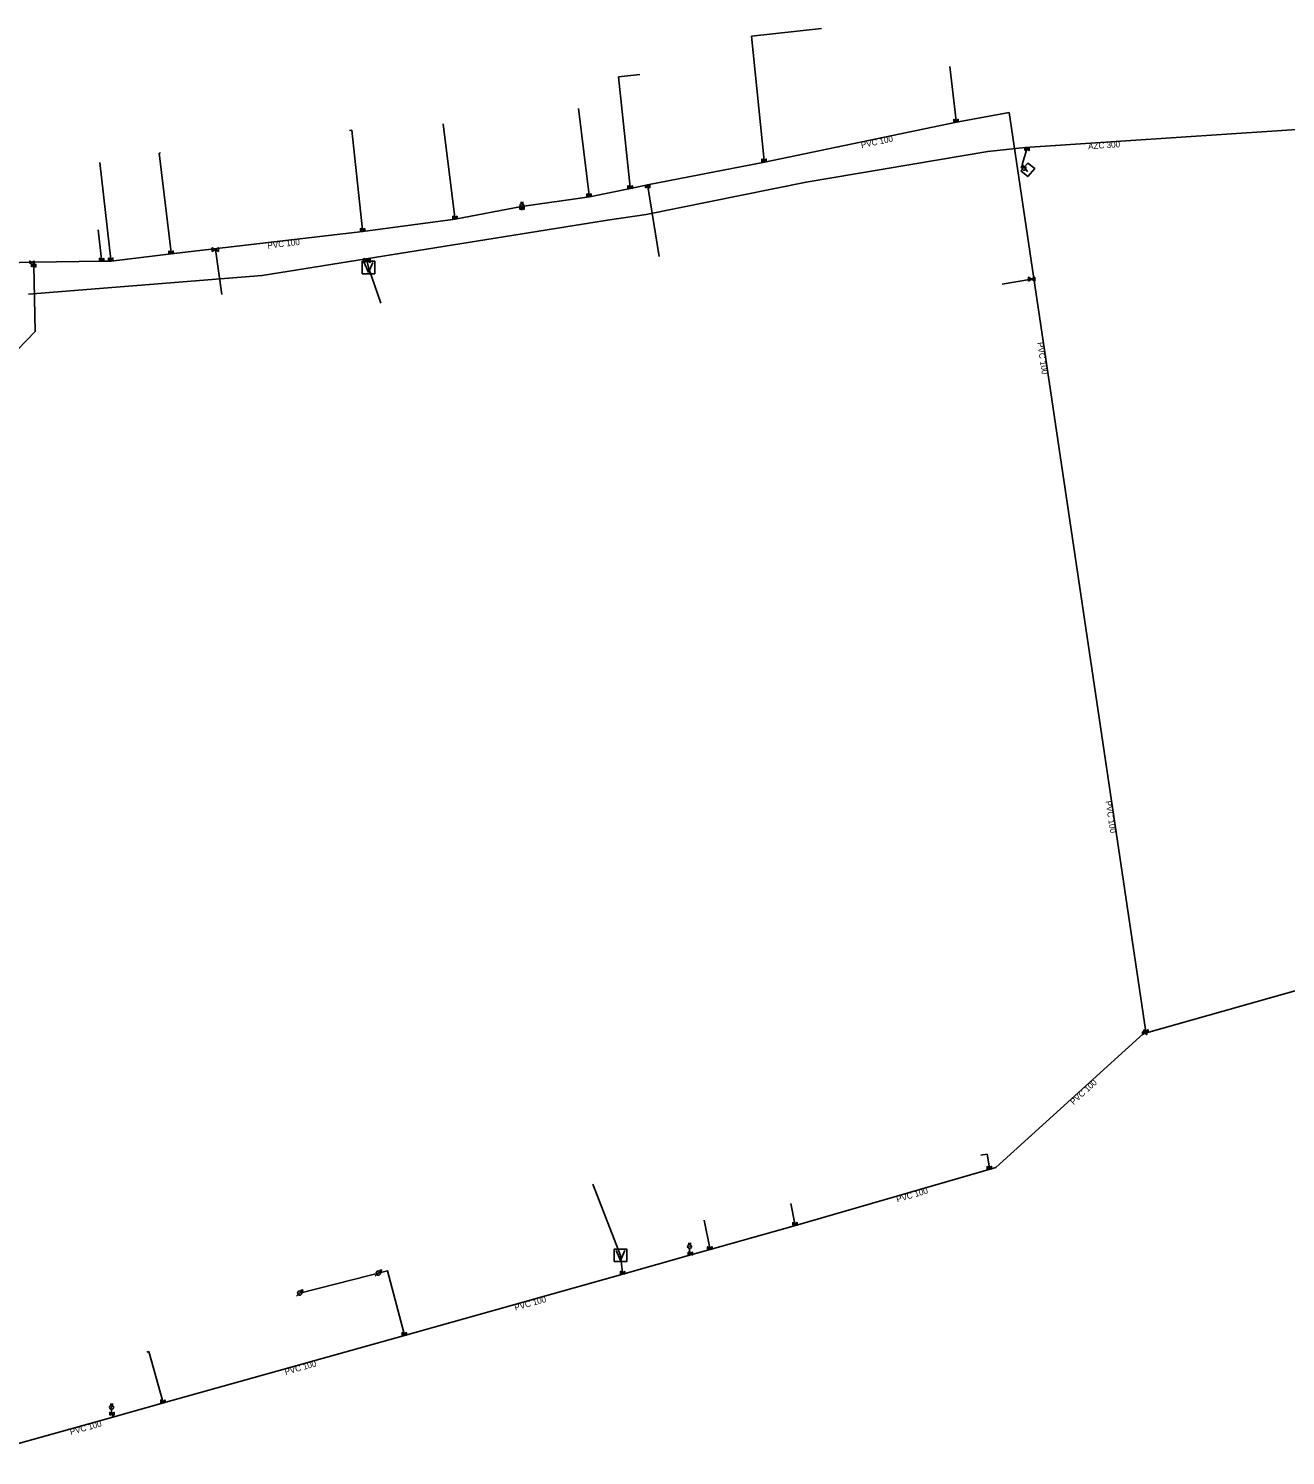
# Model space of a CAD drawing. Extents: x -523120 to -513568, y -1130571 to -1128904.
# Drawn here: x -518438 to -518236.1, y -1130098.8 to -1129869.7 of the extents above; entities that cross this region are included whole.
import ezdxf

# ---------------------------------------------------------------- set-up
doc = ezdxf.new("R2010")
doc.units = 0
for name, color, linetype in [('Default', 7, 'Continuous'), ('MoLevel 10', 7, 'Continuous'), ('MoLevel 11', 7, 'Continuous'), ('MoLevel 12', 7, 'Continuous'), ('MoLevel 13', 7, 'Continuous'), ('MoLevel 15', 7, 'Continuous'), ('MoLevel 17', 7, 'Continuous'), ('MoLevel 32', 7, 'Continuous')]:
    doc.layers.add(name, color=color, linetype=linetype)

# ---------------------------------------------------------------- blocks, each defined once
blk = doc.blocks.new('0.10')
at = {"layer": 'Default'}
for p, q in [((-0.00005, -0.00005), (0.00005, 0.00005)), ((0.00005, 0.00005), (0.00002, 0.000045)), ((0.00005, 0.00005), (0.000045, 0.00002))]:
    blk.add_line(p, q, dxfattribs=at)
blk.add_circle((0, 0), 0.000035, dxfattribs=at)
blk = doc.blocks.new('0.01')
at = {"layer": 'Default'}
blk.add_lwpolyline([(-0.00005, -0.00003), (0.00005, 0.00003), (0.00005, -0.00003), (-0.00005, 0.00003), (-0.00005, -0.00003)], dxfattribs=at)
blk = doc.blocks.new('0.05')
at = {"layer": 'Default'}
for p, q in [((-0.00001, 0.00005), (0.00001, 0.00005)), ((-0.000009, 0.000021), (0.000009, 0.000039)), ((0, 0.0000425), (0, 0.00005)), ((0, 0), (0, 0.0000175))]:
    blk.add_line(p, q, dxfattribs=at)
blk.add_circle((0, 0.00003), 0.0000125, dxfattribs=at)
blk = doc.blocks.new('0.04')
at = {"layer": 'Default'}
for p, q in [((-0.00001, 0.00005), (0.00001, 0.00005)), ((0, 0.0000425), (0, 0.00005)), ((0, 0), (0, 0.0000175))]:
    blk.add_line(p, q, dxfattribs=at)
blk.add_circle((0, 0.00003), 0.0000125, dxfattribs=at)
blk = doc.blocks.new('0.12')
at = {"layer": 'Default'}
for q in [(-0.000035, 0.00004), (0.000035, 0.00004)]:
    blk.add_line((0, -0.00004), q, dxfattribs=at)
blk.add_lwpolyline([(-0.00005, -0.00005), (0.00005, -0.00005), (0.00005, 0.00005), (-0.00005, 0.00005), (-0.00005, -0.00005)], dxfattribs=at)

msp = doc.modelspace()

# ---------------------------------------------------------------- linework, layer by layer
at = {"layer": 'MoLevel 10'}
for p, q in [((-518288.98, -1129884.77), (-518280.52, -1129883.17)), ((-518280.52, -1129883.17), (-518258.57, -1130030.46)), ((-518319.81, -1129891.14), (-518288.98, -1129884.77)), ((-518338.6, -1129894.82), (-518319.81, -1129891.14)), ((-518277.53, -1129892.64), (-518278.38, -1129891.55)), ((-518347.93, -1129896.73), (-518341.34, -1129895.41)), ((-518341.34, -1129895.41), (-518338.6, -1129894.82)), ((-518358.81, -1129898.28), (-518347.93, -1129896.73)), ((-518358.81, -1129898.28), (-518358.77, -1129898.55)), ((-518358.77, -1129898.55), (-518358.77, -1129898.88)), ((-518415.1, -1129905.9), (-518384.32, -1129902.29)), ((-518437.2, -1129907.25), (-518437.19, -1129907.77)), ((-518426.28, -1129907.07), (-518424.78, -1129907.04)), ((-518424.78, -1129907.04), (-518415.1, -1129905.9)), ((-518437.19, -1129907.77), (-518436.94, -1129918.37)), ((-518436.94, -1129918.37), (-518442.71, -1129924.22)), ((-517973.51, -1129950.32), (-518258.43, -1130030.95)), ((-518258.99, -1130031.11), (-518282.65, -1130052.61)), ((-518258.99, -1130031.11), (-518258.75, -1130031.04)), ((-518258.75, -1130031.04), (-518258.43, -1130030.95)), ((-518258.5, -1130030.7), (-518258.57, -1130030.46)), ((-518258.43, -1130030.95), (-518258.5, -1130030.7)), ((-518314.84, -1130061.9), (-518282.65, -1130052.61)), ((-518328.51, -1130065.76), (-518314.84, -1130061.9)), ((-518331.69, -1130066.41), (-518331.83, -1130066.04)), ((-518331.62, -1130066.64), (-518331.69, -1130066.41)), ((-518377.61, -1130079.55), (-518342.54, -1130069.73)), ((-518416.37, -1130090.4), (-518377.61, -1130079.55)), ((-518424.62, -1130092.14), (-518424.69, -1130091.85)), ((-518424.48, -1130092.66), (-518424.62, -1130092.14))]:
    msp.add_line(p, q, dxfattribs=at)
for points in [[(-518438.03, -1129912.36), (-518400.49, -1129909.38), (-518345.02, -1129900.49), (-518338.82, -1129899.59), (-518313.11, -1129894.37), (-518283.94, -1129889.44), (-518277.93, -1129888.79), (-518229.4, -1129885.62), (-518221.83, -1129886.14), (-518220.88, -1129888.52), (-518219.66, -1129893.09), (-518215.42, -1129905.46), (-518199.84, -1129951.83), (-518191.22, -1129978.15), (-518182.09, -1130005.66)], [(-518278.38, -1129891.55), (-518277.64, -1129889.1), (-518277.65, -1129888.77)], [(-518384.32, -1129902.29), (-518369.5, -1129900.3), (-518358.81, -1129898.28)], [(-518493.22, -1129908.72), (-518452.94, -1129907.66), (-518437.49, -1129907.25)], [(-518437.49, -1129907.25), (-518437.2, -1129907.25), (-518426.28, -1129907.07)], [(-518342.54, -1130069.73), (-518331.62, -1130066.64), (-518328.51, -1130065.76)], [(-518446.61, -1130098.83), (-518424.48, -1130092.66), (-518416.37, -1130090.4)]]:
    msp.add_lwpolyline(points, dxfattribs=at)
at = {"layer": 'MoLevel 15'}
for p, q in [((-518321.87, -1129870.93), (-518310.62, -1129869.71)), ((-518319.86, -1129890.89), (-518321.87, -1129870.93)), ((-518343.27, -1129877.47), (-518339.82, -1129877.1)), ((-518341.38, -1129895.16), (-518343.27, -1129877.47)), ((-518290.01, -1129875.81), (-518289.03, -1129884.52)), ((-518347.97, -1129896.48), (-518349.69, -1129882.55)), ((-518289.03, -1129884.52), (-518288.98, -1129884.77)), ((-518386.09, -1129886.02), (-518386.46, -1129886.08)), ((-518384.37, -1129902.05), (-518386.09, -1129886.02)), ((-518369.54, -1129900.05), (-518371.43, -1129885.01)), ((-518424.81, -1129906.79), (-518426.57, -1129891.22)), ((-518417.06, -1129889.7), (-518416.82, -1129889.66)), ((-518415.13, -1129905.65), (-518417.06, -1129889.7)), ((-518319.86, -1129890.89), (-518319.81, -1129891.14)), ((-518341.38, -1129895.16), (-518341.34, -1129895.41)), ((-518338.56, -1129895.07), (-518338.6, -1129894.82)), ((-518338.56, -1129895.07), (-518336.73, -1129906.29)), ((-518347.97, -1129896.48), (-518347.93, -1129896.73)), ((-518369.54, -1129900.05), (-518369.5, -1129900.3)), ((-518426.29, -1129906.82), (-518426.85, -1129902.03)), ((-518384.37, -1129902.05), (-518384.32, -1129902.29)), ((-518426.29, -1129906.82), (-518426.28, -1129907.07)), ((-518424.81, -1129906.79), (-518424.78, -1129907.04)), ((-518415.13, -1129905.65), (-518415.1, -1129905.9)), ((-518284.01, -1130050.45), (-518285.06, -1130050.63)), ((-518283.67, -1130052.64), (-518284.01, -1130050.45)), ((-518283.67, -1130052.64), (-518283.61, -1130052.88)), ((-518315.56, -1130058.39), (-518314.9, -1130061.66)), ((-518329.49, -1130061.03), (-518328.58, -1130065.52)), ((-518314.9, -1130061.66), (-518314.84, -1130061.9)), ((-518328.58, -1130065.52), (-518328.51, -1130065.76)), ((-518342.6, -1130069.49), (-518342.54, -1130069.73)), ((-518377.68, -1130079.31), (-518377.61, -1130079.55)), ((-518418.69, -1130082.15), (-518419.05, -1130082.25)), ((-518416.44, -1130090.16), (-518418.69, -1130082.15)), ((-518416.44, -1130090.16), (-518416.37, -1130090.4))]:
    msp.add_line(p, q, dxfattribs=at)
for points in [[(-518408.02, -1129905.07), (-518408.02, -1129905.21), (-518407, -1129912.41)], [(-518383.71, -1129906.69), (-518383.67, -1129906.96), (-518383.42, -1129908.08), (-518381.41, -1129913.81)], [(-518276.54, -1129909.91), (-518276.89, -1129909.95), (-518281.61, -1129910.74)], [(-518342.6, -1130069.49), (-518342.93, -1130066.7), (-518347.39, -1130055.26)], [(-518377.68, -1130079.31), (-518380.34, -1130069.16), (-518394.46, -1130072.76)]]:
    msp.add_lwpolyline(points, dxfattribs=at)
at = {"layer": 'MoLevel 17'}
msp.add_lwpolyline([(-518278.63, -1129892.54), (-518277.49, -1129891.35), (-518276.38, -1129892.2), (-518277.5, -1129893.48)], close=True, dxfattribs=at)

# ---------------------------------------------------------------- block references
at = {"layer": 'MoLevel 11'}
for p, xscale, yscale in [((-518289.03, -1129884.52), 7000, 7000), ((-518277.64, -1129889.1), 7000, 7000), ((-518319.86, -1129890.89), 7000, 7000), ((-518341.38, -1129895.16), 7000, 7000), ((-518338.56, -1129895.07), 7000, 7000), ((-518358.77, -1129898.55), 7000, 7000), ((-518347.97, -1129896.48), 7000, 7000), ((-518369.54, -1129900.05), 7000, 7000), ((-518384.37, -1129902.05), 7000, 7000), ((-518408.02, -1129905.21), 10000, 10000), ((-518437.49, -1129907.25), 7000, 7000), ((-518437.19, -1129907.77), 7000, 7000), ((-518426.29, -1129906.82), 7000, 7000), ((-518424.81, -1129906.79), 7000, 7000), ((-518415.13, -1129905.65), 7000, 7000), ((-518383.67, -1129906.96), 10000, 10000), ((-518276.89, -1129909.95), 10000, 10000), ((-518258.75, -1130031.04), 7000, 7000), ((-518258.5, -1130030.7), 7000, 7000), ((-518283.67, -1130052.64), 7000, 7000), ((-518314.9, -1130061.66), 7000, 7000), ((-518328.58, -1130065.52), 7000, 7000), ((-518331.69, -1130066.41), 7000, 7000), ((-518342.6, -1130069.49), 7000, 7000), ((-518377.68, -1130079.31), 7000, 7000), ((-518416.44, -1130090.16), 7000, 7000), ((-518424.62, -1130092.14), 7000, 7000)]:
    msp.add_blockref('0.01', p, dxfattribs=dict(at, xscale=xscale, yscale=yscale))
at = {"layer": 'MoLevel 12', "xscale": 25000, "yscale": 25000, "rotation": 49.8318482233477}
msp.add_blockref('0.04', (-518277.53, -1129892.64), dxfattribs=at)
at = {"layer": 'MoLevel 12'}
for name, p, xscale, yscale in [('0.05', (-518358.77, -1129898.88), 25000, 25000), ('0.05', (-518331.83, -1130066.04), 25000, 25000), ('0.10', (-518381.82, -1130069.54), 10000, 10000), ('0.10', (-518394.46, -1130072.76), 10000, 10000), ('0.05', (-518424.69, -1130091.85), 25000, 25000)]:
    msp.add_blockref(name, p, dxfattribs=dict(at, xscale=xscale, yscale=yscale))
at = {"layer": 'MoLevel 13', "xscale": 20000, "yscale": 20000}
for p in [(-518383.42, -1129908.08), (-518342.93, -1130066.7)]:
    msp.add_blockref('0.12', p, dxfattribs=at)

# ---------------------------------------------------------------- texts
at = {"layer": 'MoLevel 32'}
for s, rotation, p in [('PVC 100', 11.674, (-518304.2, -1129888.91)), ('AZC 300', 3.7373, (-518267.78, -1129889.1)), ('PVC 100', 6.6774, (-518399.59, -1129905.06)), ('PVC 100', 278.477, (-518276, -1129920.14)), ('PVC 100', 278.477, (-518265.02, -1129993.78)), ('PVC 100', 42.2626, (-518270.16, -1130042.58)), ('PVC 100', 16.1077, (-518298.47, -1130058.19)), ('PVC 100', 15.6396, (-518359.81, -1130075.58)), ('PVC 100', 15.6382, (-518396.73, -1130085.91)), ('PVC 100', 15.5772, (-518431.23, -1130095.55))]:
    msp.add_text(s, height=0.975, rotation=rotation, dxfattribs=at).set_placement(p)

doc.saveas('drawing.dxf')
